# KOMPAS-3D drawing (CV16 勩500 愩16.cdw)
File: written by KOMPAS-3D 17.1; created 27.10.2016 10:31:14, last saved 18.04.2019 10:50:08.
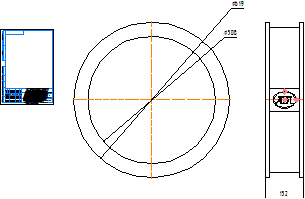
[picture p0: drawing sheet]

Sheet 1: A4, portrait

Title block, sheet 1: name: CV16 Ду500 Ру16; material: Внимание! Данный продукт является объектом авторского права ООО «Торговый Дом АДЛ». / Запрещается изменение, копирование, распространение / (в том числе путем копирования на другие сайты и ресурсы в Интернете) / или любое иное использование информации и объектов без предварительного / согласия правообладателя (ООО «Торговый Дом АДЛ»).; mass: 280,8; sheets: 1; organisation: ООО "Торговый дом АДЛ"; sheet format: A4; stored path: \\adlc.lan\data\АДЛ_ПКД\3D-модели\ADL production\Клапаны обратные ГРАНЛОК\CV16\KOMPAS 2D\CV16 Ду500 Ру16.cdw

Views: Вид 1, Проекционный вид 2
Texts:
  Klimkovich
  ADL
Dimensions and other numbers on the sheet: 619; 508; 152; 1:1; 1; 280,8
